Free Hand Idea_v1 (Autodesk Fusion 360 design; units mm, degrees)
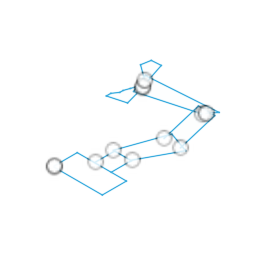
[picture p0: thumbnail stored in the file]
sketch "Sketch1" plane through (0, 0, 0) normal (0, 0, 1) x axis (1, 0, 0)
  line L1 (39.5512, -34.3098) -> (-25.483, -34.3098)
  line L2 (39.5512, -1.6341) -> (39.5512, -34.3098)
  line L3 (-27.0692, -1.6341) -> (39.5512, -1.6341)
  line L4 (-27.0692, -32.4063) -> (-27.0692, -1.6341)
  line L5 (-3.5964, 25.5138) -> (-3.5964, -0.1826)
  line L6 (18.9276, 25.5138) -> (-3.5964, 25.5138)
  line L7 (18.9276, -1.6341) -> (18.9276, 25.5138)
  line L8 (44.0976, 73.9881) -> (18.9276, 27.0366)
  line L9 (15.2287, 84.1398) -> (44.0976, 73.9881)
  line L10 (-5.387, 25.5138) -> (15.2287, 84.1398)
  line L11 (22.5917, 134.9309) -> (37.1847, 73.9881)
  line L12 (0.3849, 134.9309) -> (22.5917, 134.9309)
  line L13 (14.9779, 73.9881) -> (0.3849, 134.9309)
  line L14 (-60.6064, 108.2362) -> (12.3587, 128.2223)
  line L15 (-71.3926, 134.9309) -> (-60.6064, 108.2362)
  line L16 (21.8759, 141.5463) -> (-71.3926, 134.9309)
  line L17 (14.2621, 131.7119) -> (21.8759, 141.5463)
  line L18 (-51.2043, 90.6467) -> (-58.7595, 118.2292)
  line L19 (-73.8318, 84.4487) -> (-51.2043, 90.6467)
  line L20 (-73.8318, 90.6467) -> (-73.8318, 84.4487)
  line L21 (-68.9112, 97.8158) -> (-73.8318, 90.6467)
  line L22 (-68.9112, 102.2571) -> (-68.9112, 97.8158)
  line L23 (-66.3733, 109.5536) -> (-68.9112, 102.2571)
  line L24 (-63.9518, 116.5155) -> (-66.3733, 109.5536)
  line L25 (-72.3394, 157.5233) -> (-60.2842, 120.4062)
  line L26 (-85.0774, 156.6198) -> (-72.3394, 157.5233)
  line L27 (-87.2496, 144.1992) -> (-85.0774, 156.6198)
  line L28 (-66.3118, 128.9717) -> (-87.2496, 144.1992)
  point P10 (18.9276, -1.6341)
  point P31 (-63.9518, 116.5155)
  horizontal L1
  perpendicular L1 L2
  perpendicular L2 L3
  perpendicular L3 L4
  perpendicular L3 L5
  perpendicular L5 L6
  coincident L3 P10
  perpendicular L3 L7
  perpendicular L9 L10
  horizontal L12
  parallel L11 L13
  perpendicular L14 L18
  perpendicular L18 L19
  vertical L20
  parallel L20 L22
  coincident L15 P31
  parallel L23 L24
  parallel L16 L26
